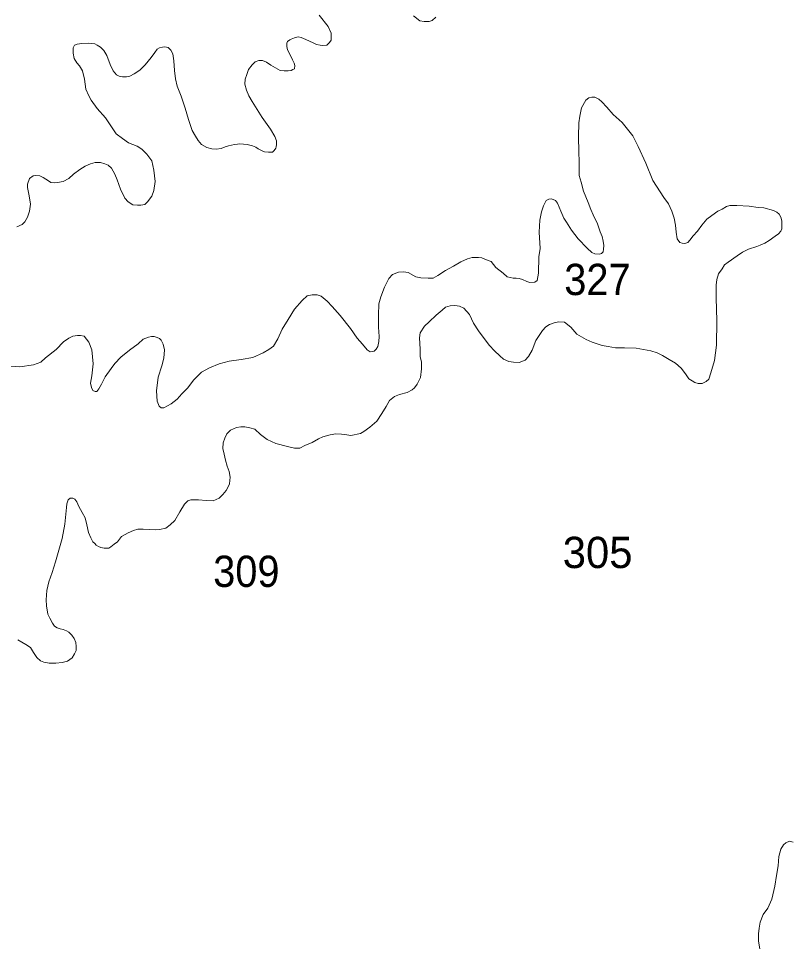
# Model space of a CAD drawing. Extents: x 445.4 to 500, y 8728.7 to 8784.
# Drawn here: x 468.782 to 472.73, y 8737.917 to 8742.638 of the extents above; entities that cross this region are included whole.
import ezdxf

# ---------------------------------------------------------------- set-up
doc = ezdxf.new("R2010")
doc.units = 0
doc.header["$LTSCALE"] = 0.064
doc.layers.add('2', color=7, linetype='Continuous', lineweight=13)
doc.layers.add('21', color=7, linetype='Continuous')

msp = doc.modelspace()

# ---------------------------------------------------------------- linework, layer by layer
at = {"layer": '2'}
for points in [[(470.1939, 8742.5392), (470.2122, 8742.5438), (470.2289, 8742.5407), (470.2517, 8742.5301), (470.2898, 8742.5134), (470.3065, 8742.5043), (470.3248, 8742.5012), (470.3385, 8742.4997), (470.3598, 8742.5012), (470.3735, 8742.5149), (470.3811, 8742.527), (470.3811, 8742.5407), (470.3811, 8742.562), (470.3659, 8742.5969), (470.3202, 8742.6547)], [(470.8025, 8742.652), (470.8351, 8742.6267), (470.8568, 8742.6231), (470.8821, 8742.6231), (470.8974, 8742.6283), (470.916, 8742.644)], [(469.0813, 8742.4105), (469.0666, 8742.4325), (469.0622, 8742.4604), (469.0625, 8742.4876), (469.0683, 8742.5008), (469.083, 8742.5066), (469.1066, 8742.5096), (469.1389, 8742.511), (469.1728, 8742.5081), (469.1845, 8742.5022), (469.2022, 8742.492), (469.2183, 8742.4743), (469.2345, 8742.4494), (469.2507, 8742.4024), (469.2669, 8742.3701), (469.2845, 8742.3496), (469.2978, 8742.3422), (469.3139, 8742.3393), (469.3345, 8742.3393), (469.3522, 8742.3437), (469.3742, 8742.354), (469.4037, 8742.3731), (469.4301, 8742.401), (469.461, 8742.4391), (469.4801, 8742.4641), (469.4919, 8742.4817), (469.5037, 8742.4876), (469.5184, 8742.492), (469.5316, 8742.4934), (469.5478, 8742.489), (469.561, 8742.4758), (469.5713, 8742.4567), (469.5772, 8742.4215), (469.5801, 8742.3716), (469.586, 8742.329), (469.5934, 8742.2909), (469.6145, 8742.2401), (469.6351, 8742.1799), (469.6512, 8742.1212), (469.6703, 8742.0654), (469.688, 8742.0361), (469.7012, 8742.014), (469.7192, 8741.9926), (469.7456, 8741.978), (469.7706, 8741.9706), (469.7927, 8741.9692), (469.8192, 8741.9721), (469.8398, 8741.9809), (469.8559, 8741.9868), (469.8721, 8741.9897), (469.8868, 8741.9926), (469.903, 8741.9956), (469.9148, 8741.997), (469.9324, 8741.9956), (469.9515, 8741.9941), (469.9795, 8741.9868), (469.9957, 8741.9794), (470.0074, 8741.9706), (470.028, 8741.9604), (470.0412, 8741.9559), (470.0604, 8741.9545), (470.081, 8741.9545), (470.0883, 8741.9604), (470.0957, 8741.9692), (470.0986, 8741.975), (470.1001, 8741.9809), (470.1015, 8741.9926), (470.1015, 8742.0117), (470.0927, 8742.0337), (470.0707, 8742.0719), (470.028, 8742.1321), (469.9775, 8742.2129), (469.9608, 8742.2417), (469.9486, 8742.2706), (469.9395, 8742.3025), (469.941, 8742.3268), (469.9501, 8742.3511), (469.9593, 8742.3769), (469.9777, 8742.401), (469.993, 8742.4161), (470.0112, 8742.4222), (470.0295, 8742.4237), (470.0508, 8742.4146), (470.0721, 8742.3994), (470.1208, 8742.3721), (470.1406, 8742.3706), (470.1619, 8742.3706), (470.1771, 8742.3721), (470.1848, 8742.3766), (470.1939, 8742.3812), (470.1954, 8742.3979), (470.1924, 8742.4101), (470.1832, 8742.4268), (470.1695, 8742.4556), (470.1589, 8742.4784), (470.1543, 8742.4951), (470.1543, 8742.5119), (470.1574, 8742.521), (470.1695, 8742.5286), (470.1771, 8742.5316), (470.1939, 8742.5392)], [(468.7744, 8741.5716), (468.8009, 8741.5834), (468.8156, 8741.5981), (468.8288, 8741.6215), (468.8391, 8741.6524), (468.8435, 8741.6876), (468.8376, 8741.7316), (468.8288, 8741.7742), (468.8279, 8741.7909), (468.8396, 8741.8188), (468.8573, 8741.8334), (468.872, 8741.8349), (468.8911, 8741.8334), (468.9088, 8741.8246), (468.9352, 8741.807), (468.9485, 8741.7997), (468.9661, 8741.7967), (468.9823, 8741.7982), (469.0117, 8741.8041), (469.0397, 8741.8202), (469.0632, 8741.8408), (469.0955, 8741.8657), (469.1235, 8741.8833), (469.1514, 8741.8951), (469.175, 8741.901), (469.2014, 8741.901), (469.2235, 8741.8951), (469.2411, 8741.8878), (469.2588, 8741.8731), (469.275, 8741.8422), (469.2867, 8741.8129), (469.3044, 8741.7645), (469.3264, 8741.7189), (469.3441, 8741.6999), (469.3676, 8741.6852), (469.3912, 8741.6823), (469.4088, 8741.6823), (469.4279, 8741.6867), (469.4426, 8741.6999), (469.4647, 8741.7292), (469.475, 8741.7586), (469.4823, 8741.8041), (469.475, 8741.8628), (469.4651, 8741.909), (469.4387, 8741.9442), (469.4137, 8741.9691), (469.3887, 8741.9853), (469.3445, 8742.0014), (469.3151, 8742.0235), (469.2813, 8742.0484), (469.2578, 8742.0836), (469.2269, 8742.1306), (469.1857, 8742.1776), (469.1549, 8742.2197), (469.1416, 8742.2417), (469.1269, 8742.2769), (469.1196, 8742.3283), (469.1107, 8742.3709), (469.0946, 8742.3958), (469.0813, 8742.4105)], [(471.6377, 8741.0233), (471.6859, 8740.9964), (471.7157, 8740.9823), (471.7667, 8740.9653), (471.7979, 8740.961), (471.8362, 8740.954), (471.8816, 8740.954), (471.9411, 8740.9511), (472.0156, 8740.9383), (472.0482, 8740.9284), (472.0765, 8740.9143), (472.1105, 8740.8945), (472.1431, 8740.8747), (472.1715, 8740.8492), (472.1927, 8740.8209), (472.2112, 8740.7955), (472.2268, 8740.7841), (472.2409, 8740.7756), (472.2579, 8740.7714), (472.2792, 8740.7714), (472.2991, 8740.7813), (472.3132, 8740.7926), (472.3232, 8740.8252), (472.3416, 8740.8888), (472.3515, 8740.9666), (472.3543, 8741.0911), (472.3504, 8741.2095), (472.3504, 8741.2731), (472.3532, 8741.3028), (472.3617, 8741.3326), (472.3802, 8741.358), (472.3929, 8741.3778), (472.4113, 8741.392), (472.457, 8741.4239), (472.4853, 8741.4423), (472.5151, 8741.4579), (472.5576, 8741.472), (472.576, 8741.4791), (472.5987, 8741.489), (472.6214, 8741.5018), (472.6512, 8741.5244), (472.6682, 8741.5371), (472.6809, 8741.5499), (472.6852, 8741.5612), (472.6866, 8741.5838), (472.6852, 8741.6036), (472.6809, 8741.622), (472.6724, 8741.6362), (472.6611, 8741.6475), (472.6441, 8741.656), (472.5944, 8741.6693), (472.5646, 8741.6707), (472.5193, 8741.6778), (472.4555, 8741.682), (472.42, 8741.6806), (472.403, 8741.6764), (472.3804, 8741.6622), (472.3591, 8741.6523), (472.3279, 8741.6297), (472.3024, 8741.6113), (472.2769, 8741.5816), (472.2556, 8741.5505), (472.2329, 8741.5264), (472.2159, 8741.5038), (472.2046, 8741.4924), (472.1904, 8741.4868), (472.1762, 8741.4882), (472.1649, 8741.4924), (472.1507, 8741.5108), (472.1465, 8741.5448), (472.1422, 8741.5816), (472.1351, 8741.6169), (472.1238, 8741.6523), (472.1068, 8741.6891), (472.0827, 8741.7216), (472.026, 8741.8094), (471.9901, 8741.8977), (471.9518, 8741.9826), (471.9249, 8742.0378), (471.8695, 8742.1051), (471.8228, 8742.1461), (471.7916, 8742.1843), (471.7661, 8742.2112), (471.7505, 8742.2254), (471.7292, 8742.2353), (471.715, 8742.2353), (471.6994, 8742.2324), (471.6838, 8742.2197), (471.6612, 8742.1801), (471.6527, 8742.1391), (471.6484, 8742.1037), (471.647, 8742.0344), (471.6484, 8741.9537), (471.6498, 8741.9056), (471.6495, 8741.8356), (471.6594, 8741.8002), (471.6722, 8741.7549), (471.6949, 8741.6969), (471.7091, 8741.6615), (471.7216, 8741.6338), (471.7428, 8741.5871)], [(471.7428, 8741.5871), (471.757, 8741.546), (471.7669, 8741.5234), (471.7726, 8741.4994), (471.7755, 8741.4767), (471.774, 8741.4583), (471.7726, 8741.4442), (471.7641, 8741.4357), (471.7528, 8741.4329), (471.7301, 8741.4343), (471.7145, 8741.4414), (471.6904, 8741.4626), (471.645, 8741.5107), (471.611, 8741.5559), (471.5855, 8741.5956), (471.5713, 8741.6168), (471.5557, 8741.6522), (471.5472, 8741.6734), (471.5387, 8741.6932), (471.5288, 8741.7073), (471.509, 8741.7158), (471.4948, 8741.7144), (471.4806, 8741.7073), (471.4679, 8741.6805), (471.4565, 8741.6493), (471.448, 8741.6055), (471.4452, 8741.5446), (471.4494, 8741.4612), (471.4438, 8741.4187), (471.4417, 8741.3345), (471.4344, 8741.2981), (471.4235, 8741.289), (471.3979, 8741.2872), (471.3815, 8741.2926), (471.3596, 8741.3036), (471.3432, 8741.3072), (471.3267, 8741.309), (471.3121, 8741.309), (471.2811, 8741.3163), (471.261, 8741.3345), (471.2227, 8741.3637), (471.199, 8741.3947), (471.1752, 8741.4038), (471.1515, 8741.4129), (471.1351, 8741.4147), (471.1022, 8741.4147), (471.0785, 8741.4092), (471.0438, 8741.3928), (471.0073, 8741.371), (470.9653, 8741.3491), (470.927, 8741.3236), (470.9033, 8741.309), (470.8777, 8741.309), (470.8394, 8741.3109), (470.8138, 8741.3163), (470.7755, 8741.3382), (470.7517, 8741.3418), (470.7262, 8741.34), (470.6952, 8741.3291), (470.6769, 8741.3072), (470.655, 8741.2635), (470.6349, 8741.2143), (470.625, 8741.1792), (470.6232, 8741.1209), (470.6232, 8741.0589), (470.6268, 8741.0116), (470.625, 8740.986), (470.6195, 8740.9605), (470.6122, 8740.946), (470.6013, 8740.9369), (470.5812, 8740.9332), (470.5648, 8740.9423), (470.541, 8740.9715), (470.5136, 8741.0024), (470.4808, 8741.0516), (470.4279, 8741.119), (470.3859, 8741.1646), (470.3603, 8741.1919), (470.3311, 8741.2174), (470.3092, 8741.2247), (470.2836, 8741.2247), (470.2581, 8741.2192), (470.2325, 8741.1956), (470.1942, 8741.1518), (470.1613, 8741.099), (470.1303, 8741.048), (470.1084, 8740.9988), (470.0865, 8740.9624), (470.0628, 8740.9441), (470.0336, 8740.9277), (469.9816, 8740.9035), (469.9213, 8740.8944), (469.8593, 8740.8852), (469.8082, 8740.8707), (469.7589, 8740.8506), (469.7187, 8740.8288), (469.6786, 8740.7905), (469.6475, 8740.7468), (469.6183, 8740.7176), (469.5946, 8740.6903), (469.5636, 8740.6666)], [(469.3935, 8740.026), (469.4199, 8740.026), (469.4822, 8740.0225), (469.5041, 8740.0238), (469.5355, 8740.0307), (469.5587, 8740.0484), (469.5819, 8740.0702), (469.6079, 8740.1152), (469.6311, 8740.1533), (469.6489, 8740.1711), (469.6639, 8740.1751), (469.7035, 8740.1751), (469.7431, 8740.1724), (469.7773, 8740.1711), (469.8087, 8740.1847), (469.8278, 8740.2024), (469.8442, 8740.2229), (469.8551, 8740.2419), (469.8619, 8740.2583), (469.8647, 8740.2924), (469.8595, 8740.3216), (469.8499, 8740.3489), (469.8417, 8740.3789), (469.8335, 8740.4102), (469.8281, 8740.4388), (469.8294, 8740.4675), (469.8376, 8740.492), (469.8472, 8740.5138), (469.8663, 8740.5315), (469.8967, 8740.546), (469.9199, 8740.5501), (469.9404, 8740.5501), (469.965, 8740.5446), (469.991, 8740.5378), (470.0196, 8740.5106), (470.0538, 8740.4847), (470.0988, 8740.4642), (470.1576, 8740.4479), (470.1945, 8740.4397), (470.2204, 8740.441), (470.2464, 8740.4533), (470.2846, 8740.4697), (470.3174, 8740.4874), (470.3392, 8740.4983), (470.3761, 8740.5078), (470.4048, 8740.5133), (470.4335, 8740.5119), (470.4621, 8740.5078), (470.4826, 8740.5051), (470.5309, 8740.516), (470.5487, 8740.5255), (470.5787, 8740.5473), (470.6143, 8740.5787), (470.6402, 8740.6169), (470.6621, 8740.6537), (470.6798, 8740.6837), (470.7058, 8740.7041), (470.7303, 8740.715), (470.7699, 8740.7246), (470.7959, 8740.7382), (470.8068, 8740.7491), (470.8205, 8740.7682), (470.8385, 8740.8016), (470.844, 8740.8466), (470.8426, 8740.8807), (470.8372, 8740.9093), (470.8358, 8740.9474), (470.8332, 8741.0038), (470.8374, 8741.0307), (470.8587, 8741.0646), (470.8828, 8741.0872), (470.9182, 8741.1212), (470.9494, 8741.1467), (470.9664, 8741.1608), (470.9905, 8741.1679), (471.0146, 8741.1707), (471.0373, 8741.1665), (471.06, 8741.1566), (471.0883, 8741.124), (471.1096, 8741.0788), (471.1351, 8741.0406), (471.1635, 8741.0009), (471.1904, 8740.9656), (471.2159, 8740.9373), (471.2443, 8740.9132), (471.2627, 8740.8962), (471.2896, 8740.8835), (471.3137, 8740.8793), (471.3429, 8740.8776), (471.3727, 8740.8903), (471.3897, 8740.9087), (471.4095, 8740.9412), (471.428, 8740.9908), (471.462, 8741.0417), (471.479, 8741.0615), (471.4974, 8741.0728), (471.5215, 8741.0813), (471.5442, 8741.087), (471.574, 8741.0841), (471.6066, 8741.0587), (471.6377, 8741.0233)], [(469.5636, 8740.6666), (469.5264, 8740.6459), (469.5118, 8740.6459), (469.5027, 8740.655), (469.4917, 8740.6805), (469.4881, 8740.7334), (469.4972, 8740.8026), (469.5155, 8740.8609), (469.5264, 8740.901), (469.5296, 8740.9439), (469.5226, 8740.9722), (469.5123, 8740.9918), (469.5037, 8741.0012), (469.4911, 8741.006), (469.4769, 8741.0115), (469.4619, 8741.0115), (469.4478, 8741.0075), (469.4202, 8740.9981), (469.3942, 8740.9745), (469.3494, 8740.9407), (469.3053, 8740.9062), (469.2746, 8740.8724), (469.2564, 8740.8472), (469.2264, 8740.8049), (469.2063, 8740.7667), (469.1935, 8740.743), (469.1826, 8740.7302), (469.1753, 8740.7302), (469.1625, 8740.7357), (469.1552, 8740.7503), (469.1515, 8740.7721), (469.157, 8740.8104), (469.1643, 8740.8723), (469.157, 8740.9434), (469.1424, 8740.9816), (469.1187, 8741.0126), (469.1004, 8741.0162), (469.084, 8741.0162), (469.0603, 8741.0126), (469.0402, 8741.0035), (469.0128, 8740.9835), (468.9745, 8740.9452), (468.9215, 8740.9015), (468.896, 8740.8796), (468.8595, 8740.8669), (468.7901, 8740.8559), (468.7171, 8740.8614)], [(468.7793, 8739.4592), (468.8195, 8739.4358), (468.8438, 8739.42), (468.8595, 8739.3946), (468.8765, 8739.3692), (468.8947, 8739.3522), (468.9129, 8739.3449), (468.9396, 8739.3413), (468.9736, 8739.3413), (469.0063, 8739.3437), (469.033, 8739.351), (469.0573, 8739.3679), (469.0694, 8739.3885), (469.0767, 8739.4055), (469.0767, 8739.4261), (469.0755, 8739.4466), (469.067, 8739.4672), (469.0561, 8739.4842), (469.0403, 8739.4987), (469.0282, 8739.506), (469.0112, 8739.5132), (468.9954, 8739.5169), (468.9808, 8739.5217), (468.9675, 8739.529), (468.9566, 8739.5447), (468.942, 8739.5702), (468.9323, 8739.5907), (468.9262, 8739.6331), (468.9238, 8739.6646), (468.9276, 8739.7125), (468.9373, 8739.7573), (468.9543, 8739.8045), (468.9713, 8739.859), (469.0065, 8739.9783), (469.0198, 8740.0522), (469.0272, 8740.1363), (469.0296, 8740.1557), (469.0369, 8740.1763), (469.0466, 8740.1847), (469.0611, 8740.1847), (469.0708, 8740.1799), (469.0805, 8740.1654), (469.0915, 8740.1424), (469.1084, 8740.1109), (469.123, 8740.0842), (469.1327, 8740.0479), (469.1412, 8740.0092), (469.1521, 8739.9813), (469.163, 8739.9619), (469.1727, 8739.9523), (469.18, 8739.9438), (469.1922, 8739.9365), (469.2031, 8739.9317), (469.2201, 8739.928), (469.231, 8739.928), (469.2443, 8739.9293), (469.254, 8739.9353), (469.2722, 8739.9486), (469.2892, 8739.9619), (469.3098, 8739.9886), (469.3426, 8740.008), (469.3705, 8740.0189), (469.3935, 8740.026)], [(472.7433, 8738.4258), (472.7255, 8738.4294), (472.7058, 8738.4223), (472.6951, 8738.4116), (472.6808, 8738.3885), (472.6701, 8738.3511), (472.6666, 8738.3048), (472.6594, 8738.2549), (472.6505, 8738.1997), (472.6345, 8738.1338), (472.6148, 8738.0875), (472.5913, 8738.0544), (472.5752, 8738.0152), (472.5699, 8737.9849), (472.5663, 8737.9565), (472.5663, 8737.9191)], [(472.5663, 8737.9191), (472.577, 8737.8585)]]:
    msp.add_lwpolyline(points, dxfattribs=at)

# ---------------------------------------------------------------- texts
at = {"layer": '21', "width": 0.95}
for s, p in [('327', (471.5735, 8741.2232)), ('309', (469.7782, 8739.7304))]:
    msp.add_text(s, height=0.16, dxfattribs=at).set_placement(p)
at = {"layer": '21'}
msp.add_text('305', height=0.16, dxfattribs=at).set_placement((471.5654, 8739.8269))

doc.saveas('drawing.dxf')
